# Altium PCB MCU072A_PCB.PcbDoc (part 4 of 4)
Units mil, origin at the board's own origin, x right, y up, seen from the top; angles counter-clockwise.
Board outline 2661.1 x 1953.35 mil, 8 copper layers (Top Layer, Mid-Layer 2, Mid-Layer 3, Mid-Layer 4, Mid-Layer 5, Mid-Layer 6, Mid-Layer 7, Bottom Layer), stack 61.2 mil thick; 186 components, 165 nets, 716 pads, 419 vias.
Unrouted connection lines stored in the file: 1.
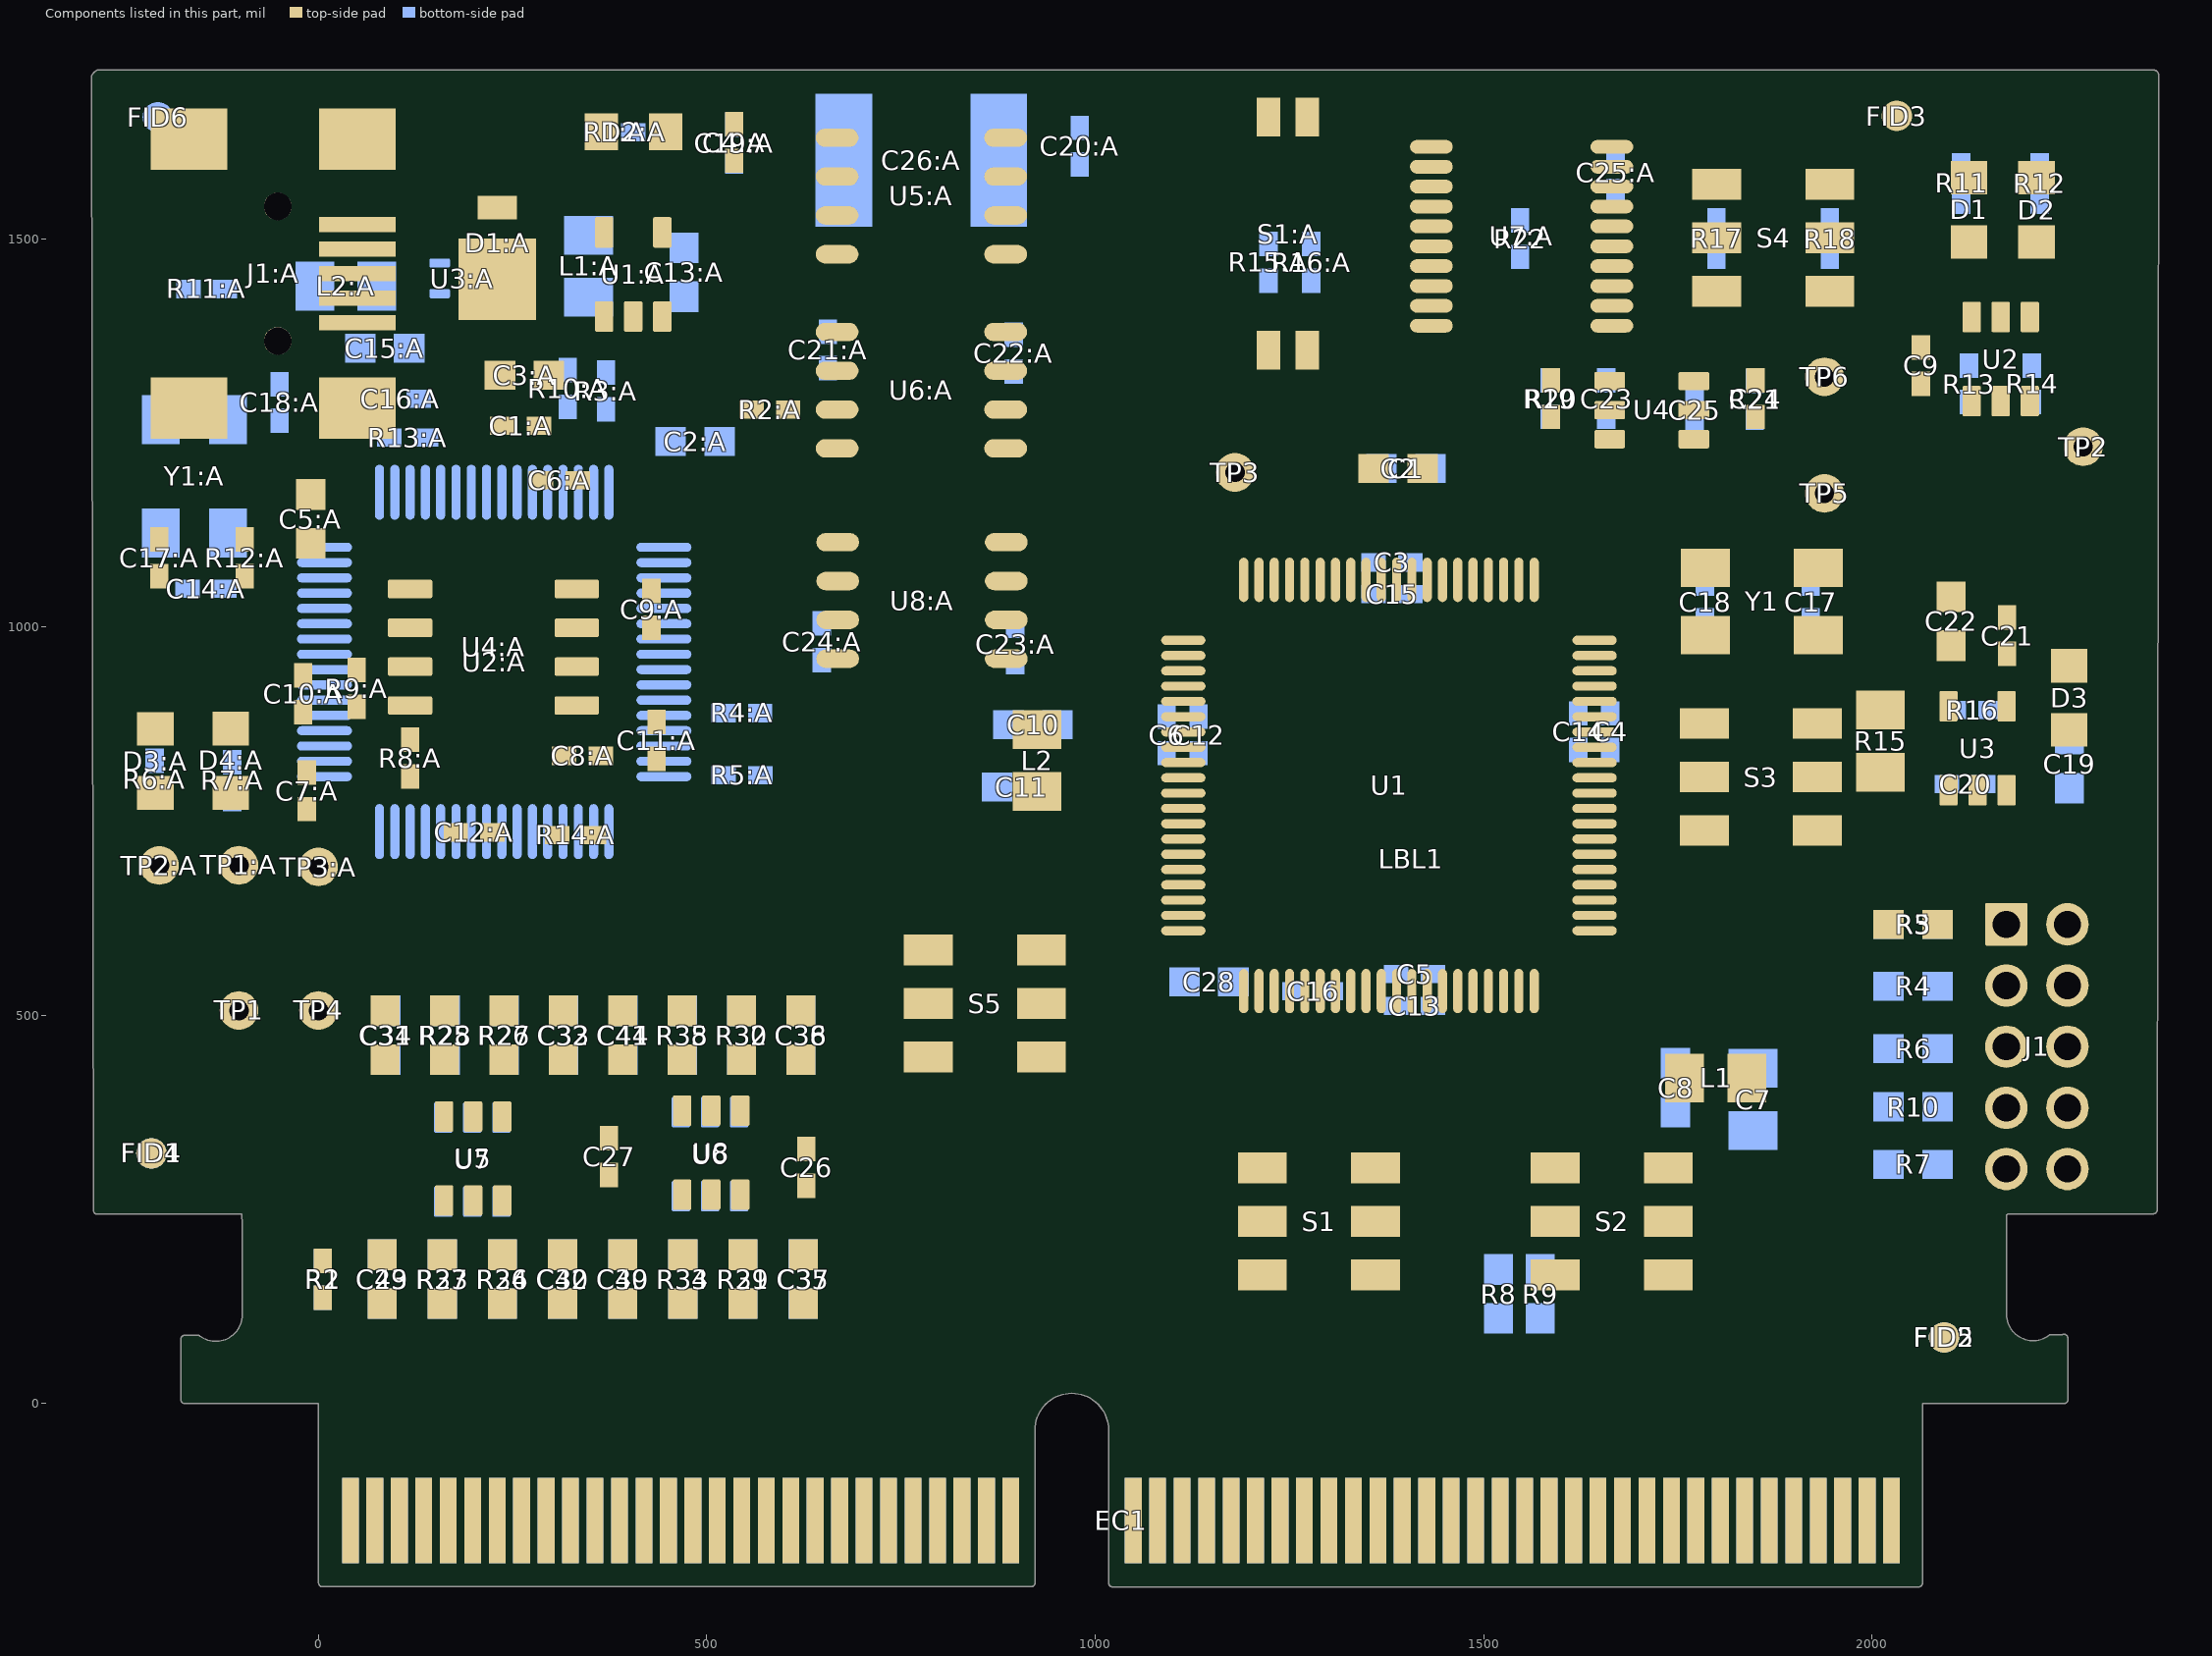
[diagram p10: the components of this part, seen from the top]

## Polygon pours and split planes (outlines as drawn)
3V3 on Mid-Layer 6 "MID-LAYER_6_3V3_P051" (solid, remove dead copper, pour order 51): 747.67,127.68 966.67,346.68 1316.67,346.68 1357.51,387.52 1399.34,345.68 1768.52,345.68 1796.67,373.83 1796.67,450.68 1725.67,521.68 1664.67,521.68 1664.67,618.68 1739.67,693.68 1739.67,875.04 1741.09,1100.1 1711.67,1129.51 1589.5,1251.68 1086.67,1251.68 1019.67,1184.68 1019.67,812.68 1019.36,813 1019.36,827.68 863.99,827.68 825.35,866.32 825.35,1712.47 2361.83,1712.47 cw(c2361.83,1707.46) 2366.84,1707.46 2366.81,1707.04 2366.81,856.97 2367.1,856.68 2084.67,856.68 2059.67,831.68 2059.67,197.68 1959.67,97.68 747.67,95.68
MCU_1V2 on Mid-Layer 6 "MID-LAYER_6_MCU_1V2_P049" (solid, remove dead copper, pour order 49): 1016.3,811.61 ccw(c1020,815) 1020,809.99 1109,809.99 ccw(c1109,815) 1113.01,811.99 ccw(c1110,816) 1115.02,816 1115.02,1021.92 1122.08,1028.99 1165,1028.99 ccw(c1165,1034) 1168.56,1030.47 1168.55,1030.45 1195.08,1056.99 1539.92,1056.99 1608.99,987.92 1608.99,821.06 1562.86,773.01 1534,773.01 ccw(c1534,768) 1530.44,771.53 1530.45,771.55 1428.45,669.55 1428.47,669.56 ccw(c1432,666) 1426.99,666 1426.99,614.51 ccw(c1432,614.51) 1428.47,610.94 1428.45,610.96 1518.96,520.45 1518.94,520.47 ccw(c1522.51,524) 1522.51,518.99 1665,518.99 ccw(c1665,524) 1670.02,524 1670.02,618.92 1743.55,692.45 1743.53,692.44 ccw(c1740,696) 1745.02,696 1745.02,877.34 1746.43,1102.38 ccw(c1741.42,1102.42) 1746.43,1102.39 1746.43,1102.38 ccw(c1741.42,1102.42) 1746.43,1102.42 ccw(c1741.42,1102.42) 1744.94,1105.98 1744.96,1105.96 1715.56,1135.36 1593.38,1257.55 1593.39,1257.53 ccw(c1589.83,1254) 1589.83,1259.01 1087,1259.01 ccw(c1087,1254) 1083.44,1257.53 1083.45,1257.55 1016.45,1190.55 1016.47,1190.56 ccw(c1020,1187) 1014.99,1187 1014.99,831.75 ccw(c1019.68,830) 1014.67,830 1014.67,815.32 ccw(c1019.68,815.32)
MCU_3V3 on Mid-Layer 6 "MID-LAYER_6_MCU_3V3_P050" (solid, remove dead copper, pour order 50): 1352.82,389.83 1352.82,562.09 1265.45,649.45 1265.47,649.44 cw(c1269,653) 1263.99,653 1263.99,755.78 1208.78,810.99 1110,810.99 cw(c1110,816) 1104.99,816 1104.99,1024 cw(c1110,1024) 1106.47,1027.56 1106.45,1027.55 1116.45,1037.55 1116.44,1037.53 cw(c1120,1034) 1120,1039.01 1162.92,1039.01 1189.45,1065.55 1189.44,1065.53 cw(c1193,1062) 1193,1067.01 1542,1067.01 cw(c1542,1062) 1545.56,1065.53 1545.55,1065.55 1617.55,993.55 1617.53,993.56 cw(c1614,990) 1619.02,990 1619.02,819.04 cw(c1614,819.04) 1617.62,815.57 cw(c1614,819.04) 1617.61,815.57 1617.62,815.57 1617.61,815.57 1568.62,764.53 1568.61,764.52 ccw(c1565,768) 1568.62,764.53 cw(c1565,768) 1565,762.99 1536.08,762.99 1437.02,663.92 1437.02,616.58 1524.58,529.01 1726,529.01 cw(c1726,524) 1729.56,527.53 1729.55,527.55 1800.55,456.55 1800.53,456.56 cw(c1797,453) 1802.02,453 1802.02,376.15 cw(c1797,376.15) 1800.53,372.59 1800.55,372.6 1772.4,344.45 1772.41,344.47 cw(c1768.85,348) 1768.85,342.99 1399.66,342.99 cw(c1399.66,348) 1396.1,344.47 1396.12,344.45 1354.29,386.29 1354.3,386.27 cw(c1357.83,389.83)
EMU_1V8 on Mid-Layer 6 "MID-LAYER_6_EMU_1V8_P038" (solid, remove dead copper, pour order 38): 2.26,823.34 2.26,1040.31 -17.61,1060.18 -48.61,1060.18 -88.35,1099.92 -88.35,1140.85 -78.41,1150.79 -34.7,1150.79 11.4,1196.89 322.16,1196.89 334.48,1184.57 334.48,1117.01 316.2,1098.73 283.73,1098.73 266,1116.46 266,1142.57 263.35,1145.23 150.09,1145.23 139.76,1134.89 139.76,903.21 175.92,867.05 314.21,867.05 370.24,811.02 370.24,778.83 338.45,747.04 268.11,747.04 234.34,780.81 198.15,817 153.9,817 121.29,784.39 41.2,784.39
EMU_3V3 on Mid-Layer 6 "MID-LAYER_6_EMU_3V3_P039" (solid, remove dead copper, pour order 39): -291.75,648 -291.75,1710.07 cw(c-284.72,1710.07) -289.69,1715.04 -289.66,1715.07 ccw(c-288.23,1713.64) -289.67,1715.05 cw(c-288.26,1713.62) -289.66,1715.07 cw(c-284.69,1710.1) -284.69,1717.13 726,1717.13 cw(c726,1715.11) 728.02,1715.11 728.02,909 cw(c726,909) 727.42,907.58 727.43,907.58 cw(c726,909) 727.42,907.57 727.43,907.58 467.42,647.57 ccw(c466,649) 467.43,647.58 467.42,647.58 cw(c466,649) 466,646.99 -287.99,646.99 cw(c-289.73,648)
MCU_A_3V3 on Mid-Layer 6 "MID-LAYER_6_MCU_A_3V3_P037" (solid, remove dead copper, pour order 37): 258.44,-103.53 ccw(c262,-100) 262,-105.01 626,-105.01 ccw(c626,-100) 629.56,-103.53 629.55,-103.55 714.55,-18.55 714.53,-18.56 ccw(c711,-15) 716.02,-15 716.02,58.92 751.55,94.45 751.53,94.44 ccw(c748,98) 753.02,98 753.02,127.92 969.08,343.99 1317,343.99 ccw(c1317,349) 1320.56,345.47 1320.55,345.45 1361.38,386.29 1361.36,386.27 ccw(c1357.83,389.83) 1362.85,389.83 1362.85,564.17 ccw(c1357.83,564.17) 1361.36,567.73 1361.38,567.71 1274.02,655.08 1274.02,757.86 ccw(c1269,757.86) 1272.53,761.42 1272.55,761.4 1215.4,818.55 1215.42,818.53 ccw(c1211.86,815) 1211.86,820.01 1025.02,820.01 1025.02,914 ccw(c1020,914) 1014.99,914 1014.99,835.02 866.39,835.02 829.22,872.18 ccw(c825.68,868.64) 821,866.82 505.2,551.01 53.59,551.01 ccw(c49,549) 44.41,551.01 -289.73,551.01 ccw(c-289.73,549) -289.73,546.99 43.99,546.99 43.99,113 ccw(c49,113) 45.47,109.44 45.45,109.45
HSEC_5V0 on Mid-Layer 6 "MID-LAYER_6_HSEC_5V0_P030" (solid, remove dead copper, pour order 30): -179.21,4.84 ccw(c-172.18,4.84) -170.79,-2.05 -1.96,-2.05 -1.96,-231.05 ccw(c5.07,-231.05) 6.05,-238.01 927.51,-238.01 ccw(c927.51,-230.98) 934.54,-230.98 ccw(c927.63,-230.98) 934.33,-229.29 934.33,-35.18 934.42,-34.31 cw(c974.39,-34.21) 1014.37,-34.1 1014.37,-231.27 ccw(c1021.4,-231.27) 1016.43,-236.24 ccw(c1021.51,-231.22) 1021.47,-238.36 1034.75,-238.36 1035.66,-238.29 2070.22,-238.29 ccw(c2070.22,-231.26) 2077.25,-231.26 2077.18,-230.35 2077.18,-2.12 2247.39,-2.12 ccw(c2247.39,4.91) 2254.42,4.91 ccw(c2247.52,4.91) 2254.22,6.6 2254.22,84.13 ccw(c2247.19,84.13) 2244.83,90.76 2230.93,90.76 ccw(c2230.93,83.74) 2226.69,89.33 cw(c2207.41,114.84) 2175.43,114.72 2175.43,241.89 2362.35,242.18 ccw(c2362.35,249.21) 2367.32,244.24 ccw(c2362.31,249.3) 2369.44,249.27 2369.31,854.35 ccw(c2367.42,859) 2372.44,859 ccw(c2367.01,858.96) 2369,864.01 2085,864.01 ccw(c2084.99,859.02) 2081.44,862.53 2056.45,837.55 ccw(c2059.96,834.02) 2054.99,834 2054.99,202.08 1957.92,105.01 747.99,103.01 ccw(c747.99,98.02) 744.44,101.53 707.45,64.55 ccw(c710.96,61.02) 705.99,61 705.99,-12.92 623.92,-94.99 264.08,-94.99 54.02,115.08 54.02,546.99 506.04,546.99 ccw(c506.04,549) 508.05,549 ccw(c506.04,549) 506.04,551.01 53.59,551.01 ccw(c49,549) 44.41,551.01 -287.72,551.01 ccw(c-289.73,551.01) -291.75,551.01 -291.75,248.71 ccw(c-284.72,248.71) -284.72,241.68 -100.74,241.68 -100.74,238.74 ccw(c-93.72,238.73) -100.33,236.37 -100.33,115.84 cw(c-135.96,114.01) -100.29,113.93 cw(c-132.26,113.93) -151.53,88.42 ccw(c-155.78,82.82) -155.78,89.86 -172.11,89.86 ccw(c-172.12,82.84) -177.08,87.8 ccw(c-172.08,82.72) -179.21,82.76
GND on Mid-Layer 2 "MID-LAYER_2_GND_P042" (solid, remove dead copper, pour order 42): -177.19,82.76 cw(c-172.18,82.76) -175.72,86.31 -175.66,86.37 cw(c-172.11,82.83) -172.11,87.84 -155.78,87.84 cw(c-155.78,82.83) -152.76,86.83 ccw(c-132.26,113.93) -98.27,113.93 ccw(c-132.26,113.93) -98.31,115.56 -98.32,115.84 -98.32,236.75 cw(c-93.71,238.74) -98.73,238.74 -98.73,243.7 -284.72,243.7 cw(c-284.72,248.71) -289.73,248.71 -289.73,549 506.04,549 825.68,868.64 825.68,1714.79 2362.15,1714.79 cw(c2362.15,1709.77) 2367.17,1709.77 2367.1,1708.94 2367.42,249.27 cw(c2362.41,249.27) 2365.96,245.72 2365.9,245.66 cw(c2362.35,249.21) 2362.35,244.19 2174.88,244.19 2173.42,242.73 2173.42,114.71 ccw(c2207.4,114.83) 2227.9,87.73 cw(c2230.93,83.73) 2230.93,88.74 2245.21,88.74 cw(c2247.19,84.13) 2252.2,84.13 2252.2,6.33 cw(c2247.39,4.91) 2252.41,4.91 cw(c2247.39,4.91) 2247.39,-0.11 2075.16,-0.11 2075.16,-230.44 2075.23,-231.26 cw(c2070.22,-231.26) 2070.22,-236.28 1035.58,-236.28 1034.75,-236.35 1021.47,-236.35 cw(c1021.47,-231.33) 1017.92,-234.88 1017.86,-234.81 cw(c1021.4,-231.27) 1016.39,-231.27 1016.39,-34.1 ccw(c974.4,-34.1) 932.42,-34.1 932.32,-35.08 932.32,-229.56 cw(c927.51,-230.98) 932.53,-230.98 cw(c927.51,-230.98) 927.51,-236 5.9,-236 cw(c5.07,-231.05) 0.06,-231.05 0.06,-0.04 -171.01,-0.04 cw(c-172.18,4.84) -177.19,4.84
EMU_GND on Mid-Layer 2 "MID-LAYER_2_EMU_GND_P041" (solid, remove dead copper, pour order 41): -289.73,649 -289.73,1710.07 cw(c-284.72,1710.07) -288.26,1713.62 -288.23,1713.64 cw(c-284.69,1710.1) -284.69,1715.11 726,1715.11 726,909 466,649
GND on Mid-Layer 5 "MID-LAYER_5_GND_P046" (solid, remove dead copper, pour order 46): -177.19,82.76 cw(c-172.18,82.76) -175.72,86.31 -175.66,86.37 cw(c-172.11,82.83) -172.11,87.84 -155.78,87.84 cw(c-155.78,82.83) -152.76,86.83 ccw(c-132.26,113.93) -98.27,113.93 ccw(c-132.26,113.93) -98.31,115.56 -98.32,115.84 -98.32,236.75 cw(c-93.71,238.74) -98.73,238.74 -98.73,243.7 -284.72,243.7 cw(c-284.72,248.71) -289.73,248.71 -289.73,549 506.04,549 825.68,868.64 825.68,1714.79 2362.15,1714.79 cw(c2362.15,1709.77) 2367.17,1709.77 2367.1,1708.94 2367.42,249.27 cw(c2362.41,249.27) 2365.96,245.72 2365.9,245.66 cw(c2362.35,249.21) 2362.35,244.19 2174.88,244.19 2173.42,242.73 2173.42,114.71 ccw(c2207.4,114.83) 2227.9,87.73 cw(c2230.93,83.73) 2230.93,88.74 2245.21,88.74 cw(c2247.19,84.13) 2252.2,84.13 2252.2,6.33 cw(c2247.39,4.91) 2252.41,4.91 cw(c2247.39,4.91) 2247.39,-0.11 2075.16,-0.11 2075.16,-230.44 2075.23,-231.26 cw(c2070.22,-231.26) 2070.22,-236.28 1035.58,-236.28 1034.75,-236.35 1021.47,-236.35 cw(c1021.47,-231.33) 1017.92,-234.88 1017.86,-234.81 cw(c1021.4,-231.27) 1016.39,-231.27 1016.39,-34.1 ccw(c974.4,-34.1) 932.42,-34.1 932.32,-35.08 932.32,-229.56 cw(c927.51,-230.98) 932.53,-230.98 cw(c927.51,-230.98) 927.51,-236 5.9,-236 cw(c5.07,-231.05) 0.06,-231.05 0.06,-0.04 -171.01,-0.04 cw(c-172.18,4.84) -177.19,4.84
EMU_GND on Mid-Layer 5 "MID-LAYER_5_EMU_GND_P045" (solid, remove dead copper, pour order 45): -289.73,649 -289.73,1710.07 cw(c-284.72,1710.07) -288.26,1713.62 -288.23,1713.64 cw(c-284.69,1710.1) -284.69,1715.11 726,1715.11 726,909 466,649
GND on Mid-Layer 7 "MID-LAYER_7_GND_P048" (solid, remove dead copper, pour order 48): -177.19,82.76 cw(c-172.18,82.76) -175.72,86.31 -175.66,86.37 cw(c-172.11,82.83) -172.11,87.84 -155.78,87.84 cw(c-155.78,82.83) -152.76,86.83 ccw(c-132.26,113.93) -98.27,113.93 ccw(c-132.26,113.93) -98.31,115.56 -98.32,115.84 -98.32,236.75 cw(c-93.71,238.74) -98.73,238.74 -98.73,243.7 -284.72,243.7 cw(c-284.72,248.71) -289.73,248.71 -289.73,549 506.04,549 825.68,868.64 825.68,1714.79 2362.15,1714.79 cw(c2362.15,1709.77) 2367.17,1709.77 2367.1,1708.94 2367.42,249.27 cw(c2362.41,249.27) 2365.96,245.72 2365.9,245.66 cw(c2362.35,249.21) 2362.35,244.19 2174.88,244.19 2173.42,242.73 2173.42,114.71 ccw(c2207.4,114.83) 2227.9,87.73 cw(c2230.93,83.73) 2230.93,88.74 2245.21,88.74 cw(c2247.19,84.13) 2252.2,84.13 2252.2,6.33 cw(c2247.39,4.91) 2252.41,4.91 cw(c2247.39,4.91) 2247.39,-0.11 2075.16,-0.11 2075.16,-230.44 2075.23,-231.26 cw(c2070.22,-231.26) 2070.22,-236.28 1035.58,-236.28 1034.75,-236.35 1021.47,-236.35 cw(c1021.47,-231.33) 1017.92,-234.88 1017.86,-234.81 cw(c1021.4,-231.27) 1016.39,-231.27 1016.39,-34.1 ccw(c974.4,-34.1) 932.42,-34.1 932.32,-35.08 932.32,-229.56 cw(c927.51,-230.98) 932.53,-230.98 cw(c927.51,-230.98) 927.51,-236 5.9,-236 cw(c5.07,-231.05) 0.06,-231.05 0.06,-0.04 -171.01,-0.04 cw(c-172.18,4.84) -177.19,4.84
EMU_GND on Mid-Layer 7 "MID-LAYER_7_EMU_GND_P047" (solid, remove dead copper, pour order 47): -289.73,649 -289.73,1710.07 cw(c-284.72,1710.07) -288.26,1713.62 -288.23,1713.64 cw(c-284.69,1710.1) -284.69,1715.11 726,1715.11 726,909 466,649

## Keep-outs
Keep-Out Layer:
  lines w0.5: 748,130 967,349 1317,349 1357.83,389.83 1357.83,564.17 1269,653 1269,757.86 1211.86,815 1020,815 ; 825.68,868.64 864.31,830 1019.68,830 1019.68,815.32
  text ".Layer_Name" at -3604.9,-2856.09 h60

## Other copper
Top Layer:
  region net MCU_A_3V3: 894,757 956,757 975.35,737.65 992.65,737.65 999,744 999,808 994,813 894,813
  region net 3V3: 894,845 956,845 956,890 972,906 972,933 966,939 902,939 894,931
  region net 3V3: 1815,388 1863,388 1863,467 1869,473 1869,493 1862,500 1832,500 1815,483
  region net MCU_3V3: 1783,450 1783,389 1782,388 1685.63,388 1677,395.13 1677,455 1684,462 1710,462 1722,450
  region net HSEC_5V0: 2088,740.76 2130,740.76 2182,740.76 2198,756.76 2198,770.76 2198,835.76 2191,842.76 2188,845.76 2163,845.76 2159,841.76 2159,819.76 2163,815.76 2163,765.76 2161,763.76 2111,763.76 2109,765.76 2109,815.76 2113,819.76 2113,843.76 2109,847.76 2090,847.76 2086,843.76 2086,817.76 2088,815.76
  region net NetC22_2: 1981,869.76 2080,869.76 2090,879.76 2109,879.76 2109,914.76 2107,916.76 1981,916.76 1980,915.76 1980,870.76
  region net 3V3: 1974.5,841 2063.1,841 2063.1,733 1976.5,733 1969.5,740 1969.5,757 1974.5,763
  text ".Layer_Name" at -3604.9,-2856.09 h60
Mid-Layer 3:
  text ".Layer_Name" at -3619,-2847 h60
Mid-Layer 4:
  text ".Layer_Name" at -3600,-2847 h60
Mid-Layer 2:
  text ".Layer_Name" at -3617,-2846 h60
Mid-Layer 5:
  text ".Layer_Name" at -3605,-2847 h60
Mid-Layer 7:
  text ".Layer_Name" at -3609,-2849 h60
Mid-Layer 6:
  text ".Layer_Name" at -3613,-2840 h60
Bottom Layer:
  text ".Layer_Name" at -3604.9,-2856.09 h60

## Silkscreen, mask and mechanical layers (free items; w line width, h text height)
Top Overlay:
  region: 2297.34,1707.69 2297.34,1563 2362,1563 2362,1707.69
  text "BOOT" at 1826,1619 h40
  text "1" at 1975,1616 h40
  text "ON" at 1103,1598 h40
  text "-" at 2349,1501 h70 r90
  text "GPIO32" at 2010,1438 h40 r90
  text "GPIO24" at 1761,1437 h40 r90
  text ".PCB_Rev" at 2347,1429 h50 r90
  text "JTAG ISO" at 1152,1423 h40 r90
  text "UART ISO" at 1363,1423 h40 r90
  text "OFF" at 1083,1386 h40
  text "0" at 1975,1361 h40
  text "1V2" at 1154,1135 h40
  text "XRSn" at 1962,1123 h40
  text "C2000 F28002x controlCARD" at 2348,660 h50 r90
  text "A8/C11" at 695,642 h40
  text "VREFHI" at 920.34,642 h40
  text "Pin34" at 685,574 h30
  text "Int" at 980,574 h30
  text "Pin30" at 685,436 h30
  text "Ext" at 978.33,436 h30
  text "GPIO24" at 1127,358 h40
  text "GPIO25" at 1328,358 h40
  text "Pin102" at 1402,316 h30
  text "Pin100" at 1094.46,294.9 h30
  text "Pin106" at 1779,294.9 h30
  text "Pin104" at 1473.12,273 h30
  text "Pin77" at 1402,176 h30
  text "Pin75" at 1106,157.15 h30
  text "Pin81" at 1779,157.11 h30
  text "Pin79" at 1483,138 h30
  text "GPIO26" at 1504,35 h40
  text "GPIO27" at 1709,35 h40
  text "1" at 38,-5 h40
  text "55" at 870,-9.57 h40
  text "57" at 1038.19,-9.57 h40
  text "119" at 1955.51,-9.57 h40
  text ".Layer_Name" at -3604.9,-2856.09 h60
Bottom Overlay:
  text "'.PRJ_Number' '.PCB_Rev'" at 2342.42,1654 h60
  text "3V3" at 2250,1187 h40
  text "1V2" at 1212.21,1137 h40
  text "XRSn" at 2049,1127 h40
  text "1V2" at -219,569.41 h40 r270
  text "5V5" at -114.79,568 h40 r270
  text "GND" at -11,560.53 h40 r270
  text "2" at 56,-5 h40
  text "56" at 915,-5 h40
  text "58" at 1089.37,-5 h40
  text "120" at 2022.44,-5 h40
  text ".Layer_Name" at -3604.9,-2856.09 h60
Top Paste:
  text ".Layer_Name" at -3604.9,-2856.09 h60
Bottom Paste:
  text ".Layer_Name" at -3604.9,-2856.09 h60
Top Solder:
  text ".Layer_Name" at -3604.9,-2856.09 h60
  text ".Layer_Name" at -3604.9,-2856.09 h60
Bottom Solder:
  text ".Layer_Name" at -3604.9,-2856.09 h60
Drill Guide:
  text ".Layer_Name" at -3604.9,-2856.09 h60
M1 Board Outline:
  the board outline again, w10
  text ".Layer_Name" at -3593,-2846 h60
M2 Board Dimensions:
  rectangle: -4181.9,-2272.6 -4056.9,-2147.6
  rectangle: -4056.9,-2397.6 -3681.9,-2272.6
  lines w7: -4181.9,-2272.6 -3181.9,-2272.6 ; -4056.9,-2397.6 -4056.9,-2147.6 ; -3931.9,-2397.6 -3931.9,-2147.6 ; -3681.9,-2397.6 -3681.9,-2147.6 ; -3431.9,-2397.6 -3431.9,-2147.6 ; -4181.9,-2397.6 -3181.9,-2397.6 -3181.9,-2147.6 -4181.9,-2147.6 -4181.9,-2397.6
  lines w10: -3200,-522 -3132,-522 ; -3158,-551 -3131,-523 ; -3158,-492 -3131,-522 ; -3124,823 -3056,905 ; -3122,-569 -3122,-247 ; -3122,-206 -3072,-260 -2962,-260 -2915,-203 ; -3122,-204 -3122,826 ; -3057,906 -2993,819 ; -3039,-354 -2971,-354 ; -2997,-383 -2970,-355 ; -2997,-324 -2970,-354 ; -2992,818 -2920,908 ; -2961,-569 -2961,-287 ; -2915,-204 -2915,826 -2915,911 ; -2914,-569 -2914,-247 ; -2908.04,446.62 cw(c-2964,-261) -2524.66,296.54 ; -2906.16,445.26 ccw(c-2766.4,679.92) -2855.29,421.66 ; -2906,-519 -2879,-549 ; -2906,-518 -2879,-490 ; -2906,452 cw(c-2873.55,278.02) -2843.28,452.39 ; -2904,-518 -2836,-518 ; -2904,-355 -2877,-385 ; -2904,-354 -2877,-326 ; -2902,-354 -2834,-354 ; -2888,-165 -2425,407 ; -2578,311 ccw(c-2440.48,651.43) -2523.34,293.74 ; -2560.75,344.3 cw(c-2677.61,210.86) -2522,296 ; -246,146 -196.6,146 -109.6,233 ; -183,-163 -163.6,-163 -11.6,-11 ; -129.6,233 -109.6,233 ; -109.6,213 -109.6,233 ; -31.6,-11 -11.6,-11 ; -11.6,-31 -11.6,-11 ; 2076,-30.6 2076,-10.6 ; 2096,-10.6 2076,-10.6 ; 2185,213.4 2185,233.4 ; 2205,233.4 2185,233.4 ; 2247.4,-162.6 2228,-162.6 2076,-10.6 ; 2321.4,146.4 2272,146.4 2185,233.4
  text "30" at -2719,467 h60
  text "R 39.00" at -658,119 h60
  text "R 39.00" at 2363,117 h60
  text "R 39.00" at -598,-197 h60
  text "R 39.00" at 2283,-198 h60
  text "18MIL" at -2793,-382 h60
  text "62MIL" at -2800,-546 h60
  text "GOLD FINGER" at -3281,-783 h60
  text "SIDE VIEW" at -3227,-896 h60
  text ".Layer_Name" at -3604.9,-2856.09 h60
M3 3D STEP Top:
  text ".Layer_Name" at -3604.9,-2856.09 h60
M4 3D STEP Bottom:
  text ".Layer_Name" at -3604.9,-2856.09 h60
M5 Assembly Top:
  lines w10: -4473.9,-2927.77 2126.1,-2927.77 ; -4473.9,-2724.43 2128.1,-2724.43 ; -4473.9,-2521.1 -4473.9,-3131.1 -468.9,-3131.1 2128.1,-3131.1 2128.1,-2521.1 -4473.4,-2521.1 -4473.4,-3131.1 -2897.9,-3131.1 ; -2008.9,-3131.1 -2008.9,-2521.1 ; -741.9,-2724.43 -741.9,-2521.1 ; 98.1,-2724.43 98.1,-2521.1 ; 720.1,-3137.6 720.1,-2934.77
  text "COMPONENTS MARKED 'DNP' SHOULD NOT BE POPULATED." at -3028.4,-2316.1 h60
  text "ASSEMBLY VARIANT:" at -3028.9,-2431.6 h60
  text ".VariantName" at -1992.9,-2431.6 h60
  text "PCB VIEWED FROM TOP SIDE" at -4410.4,-2653.27 h60
  text "BOARD #:" at -1933.9,-2653.27 h60
  text ".PRJ_Number" at -1388.4,-2653.27 h60
  text "REV:" at -543.9,-2653.27 h60
  text ".PCB_Rev" at -252.4,-2653.27 h60
  text "SVN REV:" at 294.1,-2653.27 h60
  text ".VersionControl_RevNumber" at 800.1,-2653.27 h60
  text "TID #:" at -1933.9,-2856.6 h60
  text ".TID" at -1388.4,-2856.6 h60
  text "PLOT NAME =" at -4410.4,-3061.94 h60
  text ".plot_File_Name" at -3604.9,-3061.94 h60
  text "GENERATED    :" at -1931.9,-3061.94 h60
  text ".Print_Date" at -1062.4,-3061.94 h60
  text ".Print_Time" at -333.4,-3061.94 h60
  text "TEXAS INSTRUMENTS" at 931.1,-3061.94 h60
M6 Assembly Bottom:
  lines w10: -4474.4,-2724.93 2127.6,-2724.93 ; -4472.4,-2928.27 2127.6,-2928.27 ; -3066.4,-3138.1 -3066.4,-2935.27 ; -2444.4,-2724.93 -2444.4,-2521.6 ; -1604.4,-2724.93 -1604.4,-2521.6 ; -337.4,-3131.6 -337.4,-2521.6 ; 551.6,-3131.6 2127.1,-3131.6 2127.1,-2521.6 -4474.4,-2521.6 -4474.4,-3131.6 -1877.4,-3131.6 2127.6,-3131.6 2127.6,-2521.6
  text "COMPONENTS MARKED 'DNP' SHOULD NOT BE POPULATED." at 1920.1,-2315.6 h60
  text ".VariantName" at 876.1,-2431.6 h60
  text "ASSEMBLY VARIANT:" at 1915.1,-2431.6 h60
  text ".VersionControl_RevNumber" at -3146.4,-2653.77 h60
  text "SVN REV:" at -2640.4,-2653.77 h60
  text ".PCB_Rev" at -2093.9,-2653.77 h60
  text "REV:" at -1802.4,-2653.77 h60
  text ".PRJ_Number" at -957.9,-2653.77 h60
  text "BOARD #:" at -412.4,-2653.77 h60
  text "PCB VIEWED FROM BOTTOM SIDE" at 2064.1,-2653.77 h60
  text ".TID" at -957.9,-2857.1 h60
  text "TID #:" at -412.4,-2857.1 h60
  text "TEXAS INSTRUMENTS" at -3277.4,-3062.44 h60
  text ".Print_Time" at -2012.9,-3062.44 h60
  text ".Print_Date" at -1283.9,-3062.44 h60
  text "GENERATED    :" at -414.4,-3062.44 h60
  text ".plot_File_Name" at 1258.6,-3062.44 h60
  text "PLOT NAME =" at 2064.1,-3062.44 h60
M9 Title Sheet:
  drawing of 57 lines, arcs and shapes, not listed
  text "1" at -3442.06,6038.9 h70
  text "2" at -946.4,6038.9 h70
  text "3" at 1542.94,6038.9 h70
  text "4" at 4049.61,6038.9 h70
  text "5" at 6548.6,6038.9 h70
  text "6" at 9053.6,6038.9 h70
  text "A" at -4598.4,4895.9 h70
  text "A" at 10201.6,4895.9 h70
  text "B" at -4598.4,2515.9 h70
  text "B" at 10201.6,2515.9 h70
  text "C" at -4598.4,140.9 h70
  text "C" at 10201.6,140.9 h70
  text "PROJECT TITLE:" at 7161.6,-1720.1 h45
  text ".PRJ_Title" at 7211.6,-1853.43 h70
  text "DESIGNED FOR:" at 7161.6,-2021.1 h45
  text ".PRJ_Customer" at 7211.6,-2161.1 h70
  text "D" at -4598.4,-2229.1 h70
  text "D" at 10201.6,-2229.1 h70
  text "FILE NAME:" at 7161.6,-2321.1 h45
  text ".PCB_File_Name_No_Path" at 7211.6,-2441.1 h70
  text "Texas Instruments (TI) and/or its licensors do not warrant the accuracy or completeness of this specification" at 2192.1,-2602.94 h45
  text "ENGINEER:" at 7161.6,-2611.1 h45
  text "LAYOUT BY:" at 8666.6,-2611.1 h45
  text "or any information contained therein. TI and/or its licensors do not warrant that this design will meet" at 2147.11,-2715.6 h45
  text ".PRJ_Engineer" at 7211.6,-2766.09 h70
  text "Texas Instruments" at 8717.1,-2766.09 h70
  text "the specifications, will be suitable for your application or fit for any particular purpose, or will operate in" at 2147.11,-2828.27 h45
  text ".Layer_Name" at -3604.9,-2856.09 h60
  text "ALTIUM DESIGNER VERSION:" at 8666.6,-2921.1 h45
  text "an implementation. TI and/or its licensors do not warrant that the design is production worthy. You should" at 2147.11,-2940.93 h45
  text "completely validate and test your design implementation to confirm the system functionality for your application." at 2192.1,-3053.6 h45
  text ".print_Scale" at 7211.6,-3054.43 h70
  text ".Application_BuildNumber" at 8717.1,-3054.43 h70
  text "1" at -3442.06,-3261.1 h70
  text "2" at -946.4,-3261.1 h70
  text "3" at 1542.94,-3261.1 h70
  text "4" at 4049.61,-3261.1 h70
  text "5" at 6548.6,-3261.1 h70
  text "6" at 9053.6,-3261.1 h70
M10 Fab Notes:
  drawing of 173 lines, arcs and shapes, not listed
  text "DESIGN INFORMATION" at 8196.12,4203.4 h60
  text "MIN. TRACK WIDTH:" at 7551.56,4023.4 h60
  text "5" at 8647.8,4023.4 h60
  text "MIL" at 8802.56,4023.4 h60
  text "MIN. CLEARANCE:" at 7551.56,3891.4 h60
  text "0.1" at 8587.8,3891.4 h60
  text "mm" at 8802.56,3891.4 h60
  text "MIN. VIA PAD SIZE:" at 7551.56,3759.4 h60
  text "22" at 8617.81,3759.4 h60
  text "MIL" at 8802.56,3759.4 h60
  text "0.05mm (2MIL)" at 8246.56,3617.69 h60
  text "MINIMUM ANNULAR RING" at 7222.33,3613.4 h60
  text "EXTERNAL" at 8954.56,3613.4 h60
  text "PER" at 7422.33,3495.4 h60
  text "IPC-D-275 CLASS 2 LEVEL C" at 7642.33,3495.4 h60
  text "MIL, HOLES" at 9130.56,3383.11 h60
  text "+/-" at 8738.1,3382.4 h60
  text "+/-" at 9592.1,3382.4 h60
  text "REGISTRATION TOLERANCES:" at 7222.33,3377.4 h60
  text "METAL" at 8422.1,3377.4 h60
  text "5" at 8998.3,3377.4 h60
  text "3" at 9831.3,3377.4 h60
  text "MIL" at 9947.56,3377.4 h60
  text "+/-" at 9592.1,3264.4 h60
  text "HOLE SIZE TOLERANCE (UNLESS OTHERWISE SPECIFIED):" at 7222.33,3259.4 h60
  text "3" at 9831.3,3259.4 h60
  text "MIL" at 9947.56,3259.4 h60
  text "MATERIAL:" at 7147.56,3049.94 h60
  text "FR-4 High Tg" at 8134,2909.61 h60
  text "FR-408" at 7568.56,2901.04 h60
  text "OTHER" at 9056.56,2901.04 h60
  text "X" at 7979.1,2897.4 h60
  text "THICKNESS:" at 7222.33,2734.04 h60
  text "X" at 7760.5,2734.04 h60
  text "OTHER" at 9243.6,2734.47 h60
  text "62 MIL (1.6mm) +/- 6MIL" at 7896.21,2732.66 h60
  text "TOLERANCE:" at 7222.33,2576.04 h60
  text "X" at 8061.63,2576.04 h60
  text "ANSI IPC-6012 TYPE 3 CLASS 2" at 8248.58,2576.04 h60
  text "OTHER +/-" at 8248.56,2420.04 h60
  text "BOW & TWIST:" at 7222.33,2263.04 h60
  text "X" at 8061.63,2263.04 h60
  text "ANSI IPC-6012 TYPE 3 CLASS 2" at 8248.58,2263.04 h60
  text "OTHER +/-" at 8248.56,2104.53 h60
  text "DRILLING:" at 7147.56,1966.04 h60
  text "REFERENCE:" at 7222.33,1849.04 h60
  text "X" at 7870.56,1849.04 h60
  text "AS SHOWN" at 8057.56,1849.04 h60
  text "X" at 8771.56,1849.04 h60
  text "NC_DRILL FILES" at 8908.56,1849.04 h60
  text "PTH COPPER THICKNESS:" at 7222.33,1691.04 h60
  text "X" at 8352.56,1691.04 h60
  text "20-30 um" at 8489.56,1691.04 h60
  text "OTHER" at 9206.56,1691.04 h60
  text "BOARD FINISH:" at 7147.56,1532.04 h60
  text "SILKSCREEN:" at 7302.78,1414.04 h60
  text "X" at 8251.56,1414.04 h60
  text "TOP" at 8377.56,1414.04 h60
  text "X" at 8761.56,1414.04 h60
  text "BOTTOM" at 8888.56,1414.04 h60
  text "SILKSCREEN COLOR:" at 7302.78,1247.04 h60
  text "X" at 8250.52,1247.04 h60
  text "WHITE" at 8377.56,1247.04 h60
  text "OTHER" at 8888.56,1247.04 h60
  text "X" at 8381.52,1087.84 h60
  text "GREEN" at 8508.56,1087.84 h60
  text "OTHER" at 9126.56,1087.84 h60
  text "SOLDER RESIST COLOR:" at 7302.78,1077.04 h60
  text "X" at 8381.52,917.84 h60
  text "MATTE" at 8508.56,917.84 h60
  text "SEMI-GLOSS" at 9126.1,917.2 h60
  text "IMMERSION GOLD (ENIG)" at 8208.56,729.32 h60
  text "ENEPIG" at 9546.1,726.04 h60
  text "SURFACE FINISH:" at 7147.56,725.04 h60
  text "X" at 8021.61,725.04 h60
  text "HARD GOLD FINGERS" at 9228,570 h60
  text "IMM. TIN/SILVER OR EQUIV" at 7477.1,568.04 h60
  text "OTHER" at 8908.56,568.04 h60
  text "X" at 8715.61,552.04 h60
  text "ARRAY/PANEL:" at 7147.56,389.04 h60
  text "CUT AND TRIM PER M1 BOARD OUTLINE" at 8208.56,384.75 h60
  text "N.C. ROUTE" at 8208.56,233.04 h60
  text "X" at 8887.56,233.04 h60
  text "V. SCORE" at 9074.56,233.04 h60
  text "CERTIFICATION:" at 7147.56,96.04 h60
  text "MATERIALS AND WORKMANSHIP FOR ALL PCBS" at 7872.56,96.04 h60
  text "TO MEET OR EXCEED THE REQUIREMENTS OF:" at 7872.56,-1.96 h60
  text "X" at 7499.06,-138.47 h60
  text "ANSI IPC-A-600F CLASS ->" at 7638.06,-138.47 h60
  text "X" at 9277.12,-138.47 h60
  text "2" at 9396.06,-138.46 h60
  text "1" at 9081.06,-139.96 h60
  text "3" at 9750.06,-139.96 h60
  text "X" at 8313.12,-297.96 h60
  text "RoHS" at 8450.06,-297.96 h60
  text "OTHER" at 9094.46,-297.96 h60
  text "PER ORDER" at 9491.52,-297.96 h60
  text "ALL BOARDS MUST MEET OR EXCEED UL94-V0 REQUIREMENTS." at 7175.1,-463.6 h60
  text "PCB MUST BEAR THE UL94V-0 UL REGISTERED MATERIAL ID NUMBER" at 7175.1,-583.6 h60
  text "ADDITIONAL REQUIREMENTS:" at 7147.56,-756.96 h60
  text "MICROSECTION:" at 7222.33,-871.96 h60
  text "YES" at 8128.06,-871.96 h60
  text "REQUIRED" at 8989.56,-1028.11 h60
  text "BARE BOARD ELEC. TEST:" at 7222.33,-1030.96 h60
  text "NONE" at 8528.06,-1030.96 h60
  text "X" at 8862.56,-1030.96 h60
  text "PER ORDER" at 9581.56,-1030.96 h60
  text ".Layer_Name" at -3604.9,-2856.09 h60
M11 Gerber Information:
  lines w10: -4473.9,-2927.77 2126.1,-2927.77 ; -4473.9,-2724.43 2128.1,-2724.43 ; -4473.9,-2521.1 -4473.9,-3131.1 -468.9,-3131.1 2128.1,-3131.1 2128.1,-2521.1 -4473.4,-2521.1 -4473.4,-3131.1 -2897.9,-3131.1 ; -2008.9,-3131.1 -2008.9,-2521.1 ; -741.9,-2724.43 -741.9,-2521.1 ; 98.1,-2724.43 98.1,-2521.1 ; 720.1,-3137.6 720.1,-2934.77
  text "ALL ARTWORK VIEWED FROM TOP SIDE" at -4410.4,-2653.27 h60
  text "BOARD #:" at -1933.9,-2653.27 h60
  text ".PRJ_Number" at -1388.4,-2653.27 h60
  text "REV:" at -543.9,-2653.27 h60
  text ".PCB_Rev" at -252.4,-2653.27 h60
  text "SVN REV:" at 294.1,-2653.27 h60
  text ".VersionControl_RevNumber" at 800.1,-2653.27 h60
  text "LAYER NAME =" at -4410.4,-2856.09 h60
  text "TID #:" at -1933.9,-2856.6 h60
  text ".TID" at -1388.4,-2856.6 h60
  text "PLOT NAME =" at -4410.4,-3061.94 h60
  text ".plot_File_Name" at -3604.9,-3061.94 h60
  text "GENERATED    :" at -1931.9,-3061.94 h60
  text ".Print_Date" at -1062.4,-3061.94 h60
  text ".Print_Time" at -333.4,-3061.94 h60
  text "TEXAS INSTRUMENTS" at 931.1,-3061.94 h60
M12 Stackup:
  drawing of 503 lines, arcs and shapes, not listed
  text "Layer" at 2394.58,5469.5 h60
  text "Name" at 2804.49,5469.5 h60
  text "Material" at 3734.23,5469.5 h60
  text "Thickness" at 4594,5469.5 h60
  text "Constant" at 5243.84,5469.5 h60
  text "Board Layer Stack" at 5813.7,5469.5 h60
  text "1" at 2394.58,5349.5 h60
  text "Top Overlay" at 2804.49,5349.5 h60
  text "2" at 2394.58,5229.5 h60
  text "Top Solder" at 2804.49,5229.5 h60
  text "Solder Resist" at 3734.23,5229.5 h60
  text "0.50mil" at 4594,5229.5 h60
  text "3.5" at 5243.84,5229.5 h60
  text "3" at 2394.58,5109.5 h60
  text "Top Layer" at 2804.49,5109.5 h60
  text "Copper" at 3734.23,5109.5 h60
  text "1.40mil" at 4594,5109.5 h60
  text "4" at 2394.58,4989.5 h60
  text "Dielectric1" at 2804.49,4989.5 h60
  text "FR-4 High Tg" at 3734.23,4989.5 h60
  text "5.00mil" at 4594,4989.5 h60
  text "4.2" at 5243.84,4989.5 h60
  text "5" at 2394.58,4869.5 h60
  text "Mid-Layer 2" at 2804.49,4869.5 h60
  text "Copper" at 3734.23,4869.5 h60
  text "1.40mil" at 4594,4869.5 h60
  text "6" at 2394.58,4749.5 h60
  text "Dielectric2" at 2804.49,4749.5 h60
  text "FR-4 High Tg" at 3734.23,4749.5 h60
  text "10.00mil" at 4594,4749.5 h60
  text "4.2" at 5243.84,4749.5 h60
  text "7" at 2394.58,4629.5 h60
  text "Mid-Layer 3" at 2804.49,4629.5 h60
  text "Copper" at 3734.23,4629.5 h60
  text "1.40mil" at 4594,4629.5 h60
  text "8" at 2394.58,4509.5 h60
  text "Dielectric3" at 2804.49,4509.5 h60
  text "FR-4 High Tg" at 3734.23,4509.5 h60
  text "5.00mil" at 4594,4509.5 h60
  text "4.2" at 5243.84,4509.5 h60
  text "9" at 2394.58,4389.5 h60
  text "Mid-Layer 4" at 2804.49,4389.5 h60
  text "Copper" at 3734.23,4389.5 h60
  text "1.40mil" at 4594,4389.5 h60
  text "10" at 2394.58,4269.5 h60
  text "Dielectric4" at 2804.49,4269.5 h60
  text "FR-4 High Tg" at 3734.23,4269.5 h60
  text "10.00mil" at 4594,4269.5 h60
  text "4.2" at 5243.84,4269.5 h60
  text "11" at 2394.58,4149.5 h60
  text "Mid-Layer 5" at 2804.49,4149.5 h60
  text "Copper" at 3734.23,4149.5 h60
  text "1.40mil" at 4594,4149.5 h60
  text "12" at 2394.58,4029.5 h60
  text "Dielectric5" at 2804.49,4029.5 h60
  text "FR-4 High Tg" at 3734.23,4029.5 h60
  text "5.00mil" at 4594,4029.5 h60
  text "4.2" at 5243.84,4029.5 h60
  text "13" at 2394.58,3909.5 h60
  text "Mid-Layer 6" at 2804.49,3909.5 h60
  text "Copper" at 3734.23,3909.5 h60
  text "1.40mil" at 4594,3909.5 h60
  text "14" at 2394.58,3789.5 h60
  text "Dielectric6" at 2804.49,3789.5 h60
  text "FR-4 High Tg" at 3734.23,3789.5 h60
  text "10.00mil" at 4594,3789.5 h60
  text "4.2" at 5243.84,3789.5 h60
  text "15" at 2394.58,3669.5 h60
  text "Mid-Layer 7" at 2804.49,3669.5 h60
  text "Copper" at 3734.23,3669.5 h60
  text "1.40mil" at 4594,3669.5 h60
  text "16" at 2394.58,3549.5 h60
  text "Dielectric7" at 2804.49,3549.5 h60
  text "FR-4 High Tg" at 3734.23,3549.5 h60
  text "5.00mil" at 4594,3549.5 h60
  text "4.2" at 5243.84,3549.5 h60
  text "17" at 2394.58,3429.5 h60
  text "Bottom Layer" at 2804.49,3429.5 h60
  text "Copper" at 3734.23,3429.5 h60
  text "1.40mil" at 4594,3429.5 h60
  text "18" at 2394.58,3309.5 h60
  text "Bottom Solder" at 2804.49,3309.5 h60
  text "Solder Resist" at 3734.23,3309.5 h60
  text "0.50mil" at 4594,3309.5 h60
  text "3.5" at 5243.84,3309.5 h60
  text "19" at 2394.58,3189.5 h60
  text "Bottom Overlay" at 2804.49,3189.5 h60
  text ".Layer_Name" at -3604.9,-2856.09 h60
M13 Component Bodies Top:
  text ".Layer_Name" at -3604.9,-2856.09 h60
M14 Component Bodies Bottom:
  text ".Layer_Name" at -3604.9,-2856.09 h60
M15 Courtyards Top:
  text ".Layer_Name" at -3604.9,-2856.09 h60
M16 Courtyards Bottom:
  text ".Layer_Name" at -3604.9,-2856.09 h60
Drill Drawing:
  circle w10: c3073.41,2424.33 r33.33
  lines w10: 2227.58,87.72 cw(c2230.59,83.8) 2230.61,88.74 2244.89,88.74 cw(c2246.88,84.13) 2251.88,84.13 2251.88,6.33 ; 2227.58,87.73 cw(c2207.08,114.83) 2173.1,114.71 2173.1,242.73 2174.56,244.19 2362.03,244.19 ccw(c2362.03,249.2) 2365.57,245.66 ; 2251.88,6.32 cw(c2247.33,4.92) 2252.09,4.91 cw(c2247.07,4.91) 2247.07,-0.11 2064.84,-0.11 2064.84,-230.44 2064.91,-231.26 cw(c2059.9,-231.26) 2059.9,-236.28 1022.14,-236.35 cw(c1022.19,-231.22) 1018.54,-234.81 cw(c1022.07,-231.28) 1017.07,-231.27 1017.07,-34.1 ccw(c969.58,-34.49) 922.1,-34.1 922,-35.08 922,-229.56 cw(c917.45,-230.97) 922.21,-230.98 cw(c917.19,-230.98) 917.19,-236 5.58,-236 cw(c4.75,-231.05) -0.26,-231.05 -0.26,-0.04 -171.33,-0.04 cw(c-172.51,4.83) -177.51,4.84 -177.51,82.76 cw(c-172.43,82.73) -175.98,86.37 cw(c-172.47,82.91) -172.43,87.84 -156.1,87.84 cw(c-156.06,82.96) -153.08,86.83 ccw(c-132.57,113.92) -98.59,113.93 ccw(c-124.32,114.26) -98.64,115.84 -98.64,236.75 cw(c-94.06,238.73) -99.05,238.74 -99.05,243.7 -285.04,243.7 cw(c-285.04,248.71) -290.05,248.71 -292.32,1709.72 cw(c-280.16,1704.84) -285.04,1717 2362.69,1717 cw(c2362.6,1710.82) 2368.68,1709.72 2367.1,249.27 cw(c2362.01,249.29) 2365.58,245.66 ; 3040.07,2091 3106.74,2091 3106.74,2157.67 3040.07,2157.67 3040.07,2091 ; 3040.07,2241 3073.41,2257.67 3106.74,2241 3090.07,2274.33 3106.74,2307.67 3073.41,2291 3040.07,2307.67 3056.74,2274.33 3040.07,2241 ; 3040.07,2557.67 3056.74,2557.67 3073.41,2541 3090.07,2557.67 3106.74,2557.67 3090.07,2574.33 3106.74,2591 3090.07,2591 3073.41,2607.67 3056.74,2591 3040.07,2591 3056.74,2574.33 3040.07,2557.67
  lines w12: 2980.28,2046 6515.36,2046 ; 2980.28,2646 6515.36,2646 ; 3531.16,1896 3531.16,2796 ; 4131,1896 4131,2796 ; 5230.68,1896 5230.68,2796 ; 5736.56,1896 5736.56,2796 ; 2980.28,1896 6515.36,1896 6515.36,2796 2980.28,2796 2980.28,1896
  text "Symbol" at 3070.28,2691 h72
  text "Count" at 3576.16,2691 h72
  text "Hole Size" at 4176,2691 h72
  text "Plated" at 5275.68,2691 h72
  text "Hole Type" at 5781.56,2691 h72
  text "2" at 3576.16,2541 h60
  text "35.43mil (0.900mm)" at 4176,2541 h60
  text "NPTH" at 5275.68,2541 h60
  text "Round" at 5781.56,2541 h60
  text "9" at 3576.16,2391 h60
  text "25.00mil (0.635mm)" at 4176,2391 h60
  text "PTH" at 5275.68,2391 h60
  text "Round" at 5781.56,2391 h60
  text "10" at 3576.16,2241 h60
  text "35.04mil (0.890mm)" at 4176,2241 h60
  text "PTH" at 5275.68,2241 h60
  text "Round" at 5781.56,2241 h60
  text "419" at 3576.16,2091 h60
  text "8.00mil (0.203mm)" at 4176,2091 h60
  text "PTH" at 5275.68,2091 h60
  text "Round" at 5781.56,2091 h60
  text "440 Total" at 3576.16,1941 h60
  text ".Layer_Name" at -3604.9,-2856.09 h60
M17 Embedded Cavity:
  text ".Layer_Name" at -3604.9,-2856.09 h60
M18 Embedded Assembly:
  text ".Layer_Name" at -3604.9,-2856.09 h60
M19 Embedded Keepout:
  text ".Layer_Name" at -3604.9,-2856.09 h60
M20 Power Plane Outlines:
  drawing of 157 lines, arcs and shapes, not listed
  text ".Layer_Name" at -3602.9,-2852.09 h60

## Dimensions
2369,1746.72 to -292,1746.72 on M2 Board Dimensions
-318.72,1717 to -28.1,-236 on M2 Board Dimensions
1644,-261 to 2027,-656 on M2 Board Dimensions
-4181.9,-2397.6 to -3181.9,-2397.6 on M2 Board Dimensions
